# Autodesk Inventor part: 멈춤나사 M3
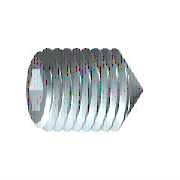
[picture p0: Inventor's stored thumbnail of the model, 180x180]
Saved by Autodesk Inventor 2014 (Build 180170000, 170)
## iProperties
Created: 2012-02
Part Number: 멈춤나사 M3
Material: 강철, 연강
Description: 6각 소켓 머리 없는 멈춤 나사
Document SubType Name: Modeling
Standard: KS B 1028
Designer: test
Standards Organization: KS
Language: ko-KR
Size Designation: 원추점 M3x8
Categories: <MemberInstance><Categories><Category DisplayName="조임쇠" InternalName="e4da775c-781d-43d5-af7c-5136215cf5a6" Mnemonic="FSTN"><Category DisplayName="볼트" InternalN
Density: 1 g/cm^3
Appearance: Steel
IsCustomPart: 1
Author: test
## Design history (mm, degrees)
sketch "스케치1"
  geometry: L1 (0, 0)-(5.5, 0); L2 (8, 0.866)-(8, 1.5); L3 (8, 1.5)-(0, 1.5); L4 (8, 0.866)-(6, 0.866); L5 (6, 0.866)-(5.5, 0); L6 (0, -0.3)-(0, 1.8) reference; L7 (0, 1.5)-(0, 0)
  constraints: 13 end point, 3 parallel, 1 collinear, 1 perpendicular, 1 point on line
  dimensions: "d0" = 2 distance of L2.start L4.end (= INTI); "d1" = 60 deg angle of L5 L1; "d2" = 3 diameter of L3 L1 (= NND); "d3" = 1.73205 diameter of L4 L1 (= 1.1547 x SW); "d5" = 8 distance from line of L2 L3.end (= NLG)
revolve "본체" sketch "스케치1" stored, may be unused: angle "d6" = 90 deg
sketch "스케치2"
  geometry: L1 (-0.433, 0.75)-(0.433, 0.75); L2 (0.433, 0.75)-(0.866, 0); L3 (0.866, 0)-(0.433, -0.75); L4 (0.433, -0.75)-(-0.433, -0.75); L5 (-0.433, -0.75)-(-0.866, 0); L6 (-0.866, 0)-(-0.433, 0.75); 3 further points
  constraints: 12 end point, 1 coincident, 1 horizontal, 13 other
extrude "슬롯" join sketch "스케치2" taper "d7" = 0 deg; stored distance "d21" = 10
workaxis "Work Axis1"
workplane "Work Plane1"
sketch "스케치4"
  geometry: L1 (0, 0.15)-(-1.35, 1.5) reference; L2 (0, -0.15)-(-1.35, -1.5) reference; L3 (-1.35, -1.5)-(0.15, 0); L4 (-1.35, 1.5)-(0.15, 0); 2 further points
  constraints: 4 end point, 1 coincident, 1 collinear, 1 horizontal alignment
workpoint "Work Point1"
body "Solid1"
feature "스레드" dims "d12" = 8 (= NLG), "d13" = 0
chamfer "모따기1" distance "d8" = 1.35 (computed from NND, SPD, FAWI); stored, may be unused: angle "d9" = 45 deg (= FAWI), second distance "d34" = 1.35 (computed from NND, SPD, FAWI)
chamfer "모따기2" distance "d10" = 0.30673 (= -0.5 x GD1 + 0.5 x NND); stored, may be unused: angle "d11" = 45 deg (= FAWI), second distance "d35" = 0.30673 (= -0.5 x GD1 + 0.5 x NND)
other parameters: "NND" = 3 [user parameter; used in 5 equation terms], "NLG" = 8 [user parameter; used in 2 equation terms], "INTI" = 2 [user parameter; used in 1 equation term], "FAWI" = 45 deg [user parameter; used in 4 equation terms], "SW" = 1.5 [user parameter; used in 2 equation terms], "GD1" = 2.38655 (= THREADDIA - 1.2269 x PTC) [user parameter; used in 2 equation terms], "d4" = 0, "FAWI1" = 45 deg [user parameter], "SPD" = 0.3 [user parameter; used in 2 equation terms], "d36" = 0, "d37" = 0, "GUL" = 0.30673 (= 0.61345 x PTC) [user parameter], "TOA" = 30 deg [user parameter], "THREADDIA" = 3 [user parameter; used in 1 equation term], "PTC" = 0.5 [user parameter; used in 4 equation terms], "GAL" = 0.30673 (= 0.61345 x PTC) [user parameter], "E0" = 1.7325 (= 1.155 x SW) [user parameter]
